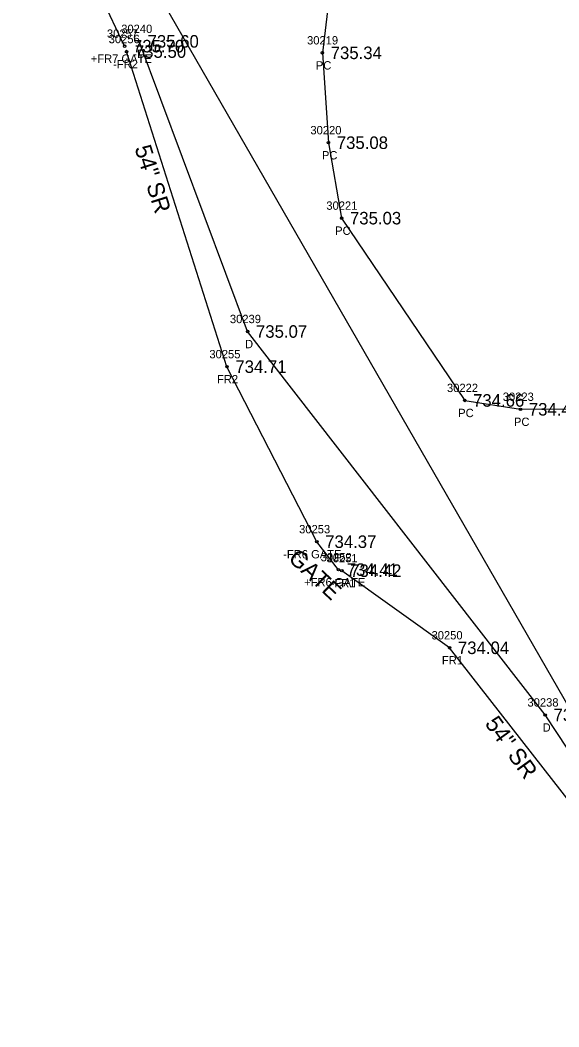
# Model space of a CAD drawing. Extents: x 1375131 to 1378678, y 999028 to 1004053.
# Drawn here: x 1376815.5 to 1376880.1, y 1002249 to 1002369.5 of the extents above; entities that cross this region are included whole.
import ezdxf

# ---------------------------------------------------------------- set-up
doc = ezdxf.new("R2010")
doc.units = 0
for name, color, linetype in [('RD_EX_Driveway', 7, 'Continuous'), ('RD_EX_Driveway_txCode', 7, 'Continuous'), ('RD_EX_DV_Prop', 7, 'Continuous'), ('RD_EX_Fence_Other', 7, 'Continuous'), ('RD_EX_Fence_Other_txCode', 7, 'Continuous'), ('RD_EX_Road', 7, 'Continuous'), ('RD_EX_RW', 7, 'Continuous'), ('RD_EX_TX_Driveway_ELEV', 7, 'Continuous'), ('RD_EX_TX_Fence_Other_ELEV', 7, 'Continuous'), ('RD_HC_Cl', 7, 'Continuous'), ('RD_SMD_Locator', 7, 'Continuous'), ('RD_TX_Misc2', 7, 'Continuous')]:
    doc.layers.add(name, color=color, linetype=linetype)

msp = doc.modelspace()

# ---------------------------------------------------------------- linework, layer by layer
at = {"layer": 'RD_EX_Driveway'}
for points in [[(1376911, 1002403.28), (1376904.12, 1002405.28), (1376902.61, 1002405.41), (1376898.14, 1002404.97), (1376891.9, 1002404.07), (1376878.32, 1002397.35), (1376865.82, 1002389.76), (1376856.77, 1002381.29), (1376852.77, 1002374.27), (1376851.72, 1002365.55), (1376852.45, 1002354.79), (1376854.03, 1002345.76), (1376868.77, 1002323.94), (1376875.45, 1002322.88), (1376882.22, 1002322.93), (1376889.24, 1002324.18), (1376897.79, 1002328.76), (1376900.27, 1002330.09), (1376914.86, 1002340.55), (1376927.38, 1002353.05), (1376934.4, 1002359.99)], [(1376893.08, 1002264.11), (1376878.41, 1002286.29), (1376842.77, 1002332.19), (1376829.79, 1002366.92)]]:
    msp.add_lwpolyline(points, dxfattribs=at)
at = {"layer": 'RD_EX_DV_Prop'}
msp.add_lwpolyline([(1376724.42, 1002117.06), (1376637.57, 1002230.63), (1376389.38, 1002558.79), (1376664.3, 1002769.81), (1376707.09, 1002654.77), (1376824.56, 1002385.67), (1376921.89, 1002216.69), (1376947.76, 1002098.6)], dxfattribs=at)
at = {"layer": 'RD_EX_Fence_Other'}
for p, q in [((1376828.04, 1002366.35), (1376821.66, 1002379.77)), ((1376853.64, 1002303.68), (1376851.06, 1002307.03))]:
    msp.add_line(p, q, dxfattribs=at)
for points in [[(1376851.06, 1002307.03), (1376840.3, 1002327.98), (1376828.27, 1002365.7)], [(1376891.67, 1002262.69), (1376866.96, 1002294.33), (1376854.05, 1002303.56)]]:
    msp.add_lwpolyline(points, dxfattribs=at)
at = {"layer": 'RD_EX_Road'}
for points in [[(1377013.31, 1002264.91), (1376982.81, 1002315.68), (1376952.47, 1002370.34), (1376923.17, 1002424.32), (1376895.64, 1002480.03), (1376870.11, 1002535.05), (1376846.33, 1002588.86), (1376822.29, 1002645.03), (1376786.56, 1002736.46)], [(1376994.75, 1002253.91), (1376964.91, 1002306.46), (1376934.4, 1002359.99), (1376904.77, 1002415.49), (1376877.27, 1002471.51), (1376851.04, 1002526.89), (1376827.48, 1002581.62), (1376804.19, 1002637.82), (1376768.46, 1002728.84)]]:
    msp.add_spline(points, degree=3, dxfattribs=at)
at = {"layer": 'RD_EX_RW'}
for radius in [2767, 2833]:
    msp.add_arc((1379404.86, 1003700.11), radius, 200.26995, 211.13117, dxfattribs=at)
at = {"layer": 'RD_HC_Cl'}
msp.add_arc((1379404.86, 1003700.11), 2800, 200.26995, 211.13117, dxfattribs=at)
at = {"layer": 'RD_SMD_Locator'}
for centre in [(1376828.04, 1002366.35), (1376829.79, 1002366.92), (1376828.27, 1002365.7), (1376851.72, 1002365.55), (1376852.45, 1002354.79), (1376854.03, 1002345.76), (1376842.77, 1002332.19), (1376840.3, 1002327.98), (1376868.77, 1002323.94), (1376875.45, 1002322.88), (1376851.06, 1002307.03), (1376853.64, 1002303.68), (1376854.05, 1002303.56), (1376866.96, 1002294.33), (1376878.41, 1002286.29)]:
    msp.add_circle(centre, 0.15, dxfattribs=at)

# ---------------------------------------------------------------- texts
at = {"layer": 'RD_EX_Driveway_txCode'}
for s, p in [('30240', (1376827.63, 1002367.92)), ('30219', (1376849.89, 1002366.55)), ('-D', (1376829.07, 1002364.92)), ('PC', (1376850.94, 1002363.55)), ('30220', (1376850.29, 1002355.79)), ('PC', (1376851.67, 1002352.79)), ('30221', (1376852.2, 1002346.76)), ('PC', (1376853.25, 1002343.76)), ('30239', (1376840.65, 1002333.19)), ('D', (1376842.46, 1002330.19)), ('30222', (1376866.65, 1002324.94)), ('30223', (1376873.33, 1002323.88)), ('PC', (1376867.99, 1002321.94)), ('PC', (1376874.67, 1002320.88)), ('30238', (1376876.29, 1002287.29)), ('D', (1376878.1, 1002284.29))]:
    msp.add_text(s, height=1, dxfattribs=at).set_placement(p)
at = {"layer": 'RD_EX_Fence_Other_txCode'}
for s, p in [('30257', (1376825.92, 1002367.35)), ('30256', (1376826.13, 1002366.7)), ('+FR7 GATE', (1376823.98, 1002364.35)), ('-FR2', (1376826.66, 1002363.7)), ('30255', (1376838.19, 1002328.98)), ('FR2', (1376839.1, 1002325.98)), ('30253', (1376848.94, 1002308.03)), ('-FR6 GATE', (1376847.03, 1002305.03)), ('30252', (1376851.52, 1002304.68)), ('30251', (1376852.22, 1002304.56)), ('+FR6 GATE', (1376849.54, 1002301.68)), ('-FR1', (1376852.72, 1002301.56)), ('30250', (1376864.8, 1002295.33)), ('FR1', (1376866.04, 1002292.33))]:
    msp.add_text(s, height=1, dxfattribs=at).set_placement(p)
at = {"layer": 'RD_EX_TX_Driveway_ELEV'}
for s, p in [('735.60', (1376830.79, 1002366.17)), ('735.34', (1376852.72, 1002364.8)), ('735.08', (1376853.45, 1002354.04)), ('735.03', (1376855.03, 1002345.01)), ('735.07', (1376843.77, 1002331.44)), ('734.66', (1376869.77, 1002323.19)), ('734.48', (1376876.45, 1002322.13)), ('733.94', (1376879.41, 1002285.54))]:
    msp.add_text(s, height=1.5, dxfattribs=at).set_placement(p)
at = {"layer": 'RD_EX_TX_Fence_Other_ELEV'}
for s, p in [('735.70', (1376829.04, 1002365.6)), ('735.50', (1376829.27, 1002364.95)), ('734.71', (1376841.3, 1002327.23)), ('734.37', (1376852.06, 1002306.28)), ('734.41', (1376854.64, 1002302.93)), ('734.42', (1376855.05, 1002302.81)), ('734.04', (1376867.96, 1002293.58))]:
    msp.add_text(s, height=1.5, dxfattribs=at).set_placement(p)
at = {"layer": 'RD_TX_Misc2'}
for s, rotation, p in [('54" SR', 287.4507, (1376829.21, 1002354.16)), ('GATE', 316.7879, (1376847.52, 1002304.88)), ('54" SR', 305.7139, (1376871.11, 1002285.24))]:
    msp.add_text(s, height=2, rotation=rotation, dxfattribs=at).set_placement(p)

doc.saveas('drawing.dxf')
